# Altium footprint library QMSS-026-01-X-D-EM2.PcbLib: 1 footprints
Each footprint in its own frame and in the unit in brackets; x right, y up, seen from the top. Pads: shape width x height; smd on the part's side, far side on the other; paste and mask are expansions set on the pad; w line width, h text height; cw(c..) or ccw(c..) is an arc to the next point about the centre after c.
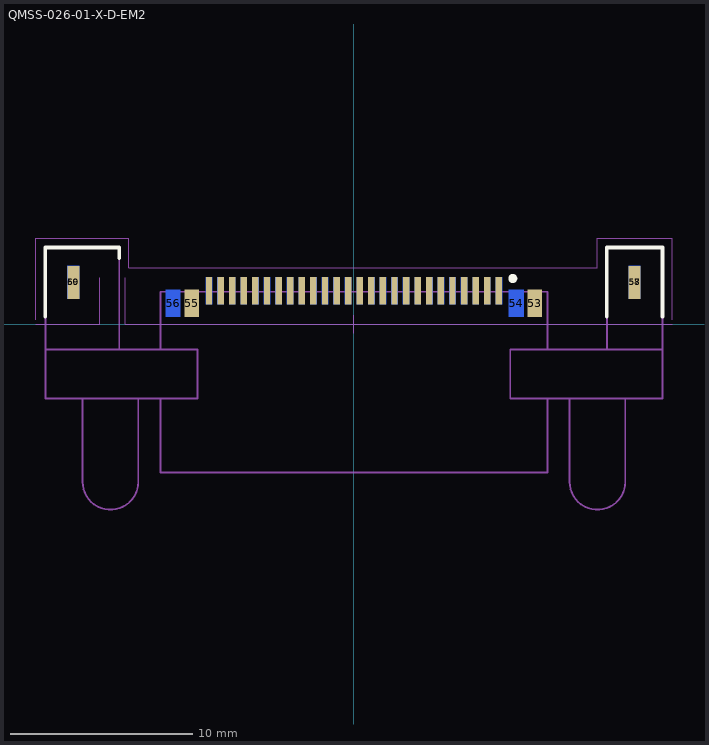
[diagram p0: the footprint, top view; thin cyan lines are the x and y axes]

## QMSS-026-01-X-D-EM2 [mm] "0.635mm pitch, 52 pin, terminal strip; shielded, double row, w/edge mounts"
height 3.63
pads (60):
  rect 0.35x1.5 smd mask+0: 1(7.937,1.829) 3(7.302,1.829) 5(6.667,1.829) 7(6.032,1.829) 9(5.397,1.829) 11(4.762,1.829) 13(4.127,1.829) 15(3.492,1.829) 17(2.857,1.829) 19(2.222,1.829) 21(1.587,1.829) 23(0.952,1.829) 25(0.317,1.829) 27(-0.318,1.829) 29(-0.953,1.829) 31(-1.588,1.829) 33(-2.223,1.829) 35(-2.858,1.829) 37(-3.493,1.829) 39(-4.128,1.829) 41(-4.763,1.829) 43(-5.398,1.829) 45(-6.033,1.829) 47(-6.668,1.829) 49(-7.303,1.829) 51(-7.938,1.829)
  rect 0.35x1.5 smd far side mask+0: 2(7.937,1.829) 4(7.302,1.829) 6(6.667,1.829) 8(6.032,1.829) 10(5.397,1.829) 12(4.762,1.829) 14(4.127,1.829) 16(3.492,1.829) 18(2.857,1.829) 20(2.222,1.829) 22(1.587,1.829) 24(0.952,1.829) 26(0.317,1.829) 28(-0.318,1.829) 30(-0.953,1.829) 32(-1.588,1.829) 34(-2.223,1.829) 36(-2.858,1.829) 38(-3.493,1.829) 40(-4.128,1.829) 42(-4.763,1.829) 44(-5.398,1.829) 46(-6.033,1.829) 48(-6.668,1.829) 50(-7.303,1.829) 52(-7.938,1.829)
  rect 0.8x1.5 smd mask+0: 53(9.906,1.143) 55(-8.89,1.143)
  rect 0.8x1.5 smd far side mask+0: 54(8.89,1.143) 56(-9.906,1.143)
  rect 0.65x1.8 smd mask+0: 57(15.367,2.286) 59(-15.367,2.286)
  rect 0.65x1.8 smd far side mask+0: 58(15.367,2.286) 60(-15.367,2.286)
Top Overlay:
  circle w0.25: c8.7,2.5 r0.125
  lines w0.2: -16.9,0.4 -16.9,4.2 -12.85,4.2 -12.85,3.6 ; 13.85,0.4 13.85,4.2 16.9,4.2 16.9,0.4
Bottom Overlay:
  lines w0.2: -16.9,0.4 -16.9,4.2 -12.85,4.2 -12.85,3.6 ; 13.85,0.4 13.85,4.2 16.9,4.2 16.9,0.4
Mechanical 12:
  lines w0.001: -17.422,0 -13.919,0 -13.919,2.553 ; -12.522,2.553 -12.522,0 17.428,0
Mechanical 13:
  lines w0.1: -14.859,-4.064 -14.859,-8.636 ccw(c-13.335,-8.636) -11.811,-8.636 -11.811,-4.064 ; -12.85,-1.397 -12.85,4.2 -16.9,4.2 -16.9,-1.397 ; -10.592,-4.064 -10.592,-8.128 10.592,-8.128 10.592,-4.064 ; -10.592,-1.397 -10.592,1.778 10.592,1.778 10.592,-1.397 ; 11.811,-4.064 11.811,-8.636 ccw(c13.335,-8.636) 14.859,-8.636 14.859,-4.064 ; 13.85,-1.397 13.85,4.2 16.9,4.2 16.9,-1.397 ; -16.9,-1.397 -16.9,-4.064 -8.56,-4.064 -8.56,-1.397 -16.9,-1.397 ; 8.56,-4.064 8.56,-1.397 16.891,-1.397 16.891,-4.064 8.56,-4.064
  lines w0.254: -7.938,1.778 -7.938,2.286 ; -7.303,1.778 -7.303,2.286 ; -6.668,1.778 -6.668,2.286 ; -6.033,1.778 -6.033,2.286 ; -5.398,1.778 -5.398,2.286 ; -4.763,1.778 -4.763,2.286 ; -4.128,1.778 -4.128,2.286 ; -3.493,1.778 -3.493,2.286 ; -2.858,1.778 -2.858,2.286 ; -2.223,1.778 -2.223,2.286 ; -1.588,1.778 -1.588,2.286 ; -0.953,1.778 -0.953,2.286 ; -0.318,1.778 -0.318,2.286 ; 0.317,1.778 0.317,2.286 ; 0.952,1.778 0.952,2.286 ; 1.587,1.778 1.587,2.286 ; 2.222,1.778 2.222,2.286 ; 2.857,1.778 2.857,2.286 ; 3.492,1.778 3.492,2.286 ; 4.127,1.778 4.127,2.286 ; 4.762,1.778 4.762,2.286 ; 5.397,1.778 5.397,2.286 ; 6.032,1.778 6.032,2.286 ; 6.667,1.778 6.667,2.286 ; 7.302,1.778 7.302,2.286 ; 7.937,1.778 7.937,2.286
  text ".Designator" at 0.254,0.254 h1.52
Mechanical 14:
  lines w0.1: -14.859,-4.064 -14.859,-8.636 ccw(c-13.335,-8.636) -11.811,-8.636 -11.811,-4.064 ; -12.85,-1.397 -12.85,4.2 -16.9,4.2 -16.9,-1.397 ; -10.592,-4.064 -10.592,-8.128 10.592,-8.128 10.592,-4.064 ; -10.592,-1.397 -10.592,1.778 10.592,1.778 10.592,-1.397 ; 11.811,-4.064 11.811,-8.636 ccw(c13.335,-8.636) 14.859,-8.636 14.859,-4.064 ; 13.85,-1.397 13.85,4.2 16.9,4.2 16.9,-1.397 ; -16.9,-1.397 -8.56,-1.397 -8.56,-4.064 -16.9,-4.064 -16.9,-1.397 ; 8.56,-4.064 16.891,-4.064 16.891,-1.397 8.56,-1.397 8.56,-4.064
  lines w0.254: -7.938,1.778 -7.938,2.286 ; -7.303,1.778 -7.303,2.286 ; -6.668,1.778 -6.668,2.286 ; -6.033,1.778 -6.033,2.286 ; -5.398,1.778 -5.398,2.286 ; -4.763,1.778 -4.763,2.286 ; -4.128,1.778 -4.128,2.286 ; -3.493,1.778 -3.493,2.286 ; -2.858,1.778 -2.858,2.286 ; -2.223,1.778 -2.223,2.286 ; -1.588,1.778 -1.588,2.286 ; -0.953,1.778 -0.953,2.286 ; -0.318,1.778 -0.318,2.286 ; 0.317,1.778 0.317,2.286 ; 0.952,1.778 0.952,2.286 ; 1.587,1.778 1.587,2.286 ; 2.222,1.778 2.222,2.286 ; 2.857,1.778 2.857,2.286 ; 3.492,1.778 3.492,2.286 ; 4.127,1.778 4.127,2.286 ; 4.762,1.778 4.762,2.286 ; 5.397,1.778 5.397,2.286 ; 6.032,1.778 6.032,2.286 ; 6.667,1.778 6.667,2.286 ; 7.302,1.778 7.302,2.286 ; 7.937,1.778 7.937,2.286
Mechanical 15:
  lines w0.05: -17.422,0.25 -17.422,4.7 -12.322,4.7 -12.322,3.1 13.328,3.1 13.328,4.7 17.428,4.7 17.428,0.25 ; -0.5,0 0.5,0 ; 0,-0.5 0,0.5
Drill Drawing:
  lines w0.001: -13.919,2.553 cw(c-13.221,2.553) -12.522,2.553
